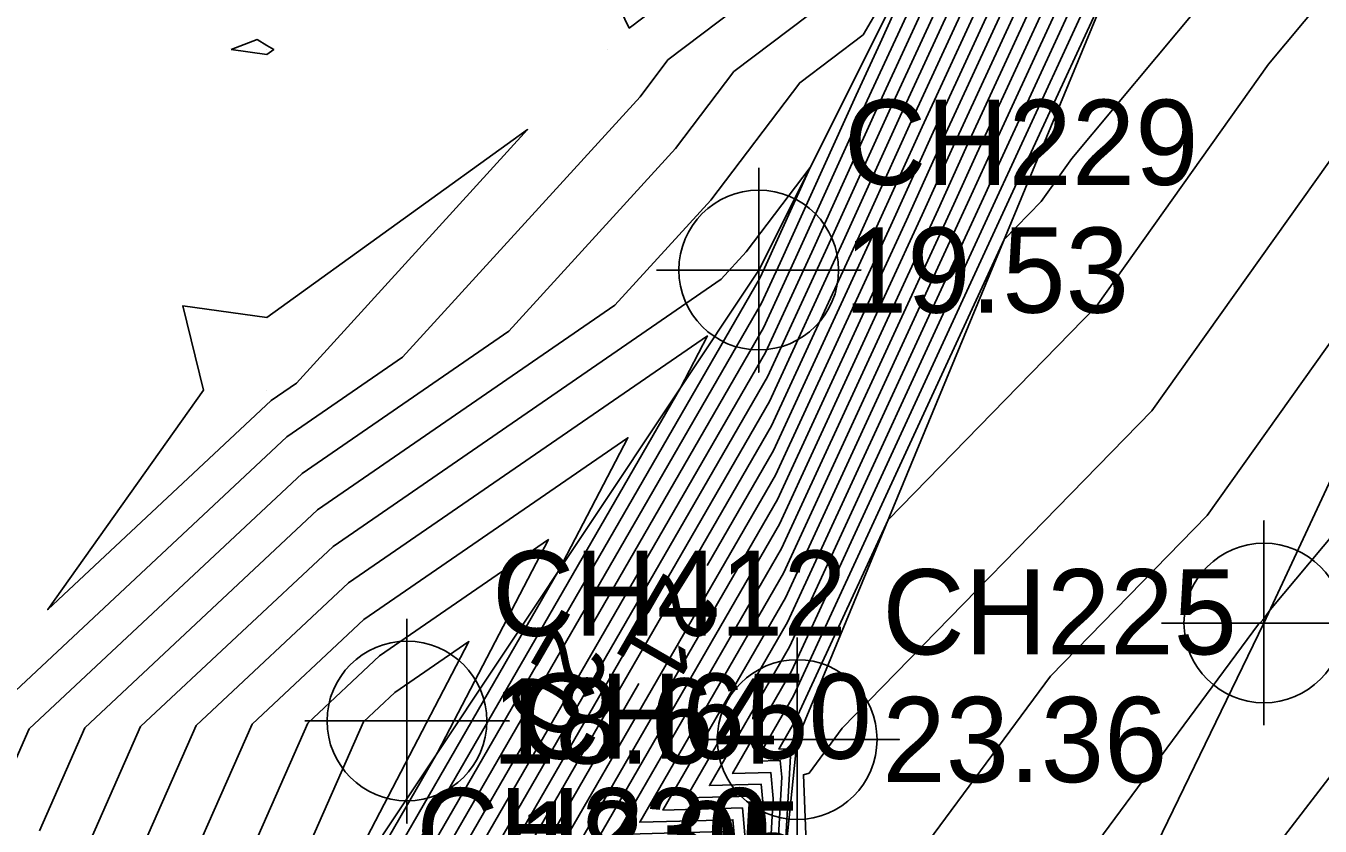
# Model space of a CAD drawing. Extents: x 2531902 to 2533249, y 715219 to 716099.
# Drawn here: x 2532842.92 to 2532880.91, y 715667.21 to 715690.69 of the extents above; entities that cross this region are included whole.
import ezdxf

# ---------------------------------------------------------------- set-up
doc = ezdxf.new("R2010")
doc.units = 0
for name, color, linetype in [('DTM Contours Major', 7, 'Continuous'), ('DTM Contours Major Text', 7, 'Continuous'), ('DTM Contours Minor', 7, 'Continuous'), ('Exist DTM Breakline', 7, 'Continuous'), ('Exist DTM Breakline Cogo Elevation', 7, 'Continuous'), ('Exist DTM Breakline Cogo Number', 7, 'Continuous'), ('Exist DTM Breakline Cogo Point CELL', 7, 'Continuous'), ('Exist DTM QL2 LIDAR Elevation Point', 7, 'Continuous'), ('Exist DTM Regular Point CELL', 7, 'Continuous'), ('Exist DTM Regular Point Cogo Elevation', 7, 'Continuous'), ('Exist DTM Regular Point Cogo Number', 7, 'Continuous'), ('Exist Roads Soil', 7, 'Continuous'), ('Exist Roads Soil Cogo Point CELL', 7, 'Continuous')]:
    doc.layers.add(name, color=color, linetype=linetype)

msp = doc.modelspace()

# ---------------------------------------------------------------- linework, layer by layer
at = {"layer": 'DTM Contours Major'}
for points in [[(2532893.313, 715749.337), (2532899.157, 715757.294), (2532891.649, 715737.361), (2532888.467, 715730.76), (2532884.29, 715720.393), (2532881.681, 715715), (2532875.656, 715701.654), (2532869.225, 715687.729), (2532867.839, 715684.677), (2532864.865, 715678.232), (2532862.915, 715674.854)], [(2532880.417, 715707.702), (2532870.834, 715686.951), (2532870.156, 715685.459), (2532865.159, 715674.632), (2532860.94, 715667.321), (2532863.673, 715667.393), (2532863.838, 715665.539), (2532863.575, 715660.867), (2532863.5, 715660.175), (2532863.284, 715660.391), (2532863.242, 715660.351), (2532863.077, 715658.749), (2532865.019, 715656.53), (2532866.863, 715655.862), (2532867.314, 715655.698), (2532867.762, 715655.577), (2532869.107, 715654.928), (2532869.992, 715654.403), (2532870.491, 715654.162), (2532874.102, 715652.417), (2532878.683, 715650.288), (2532879.268, 715650.005), (2532882.822, 715648.289)], [(2532833.041, 715658.953), (2532836.467, 715658.82), (2532841.725, 715659.565), (2532841.817, 715660.266), (2532842.154, 715668.099), (2532843.02, 715670.063), (2532851.032, 715677.56), (2532857.094, 715681.734), (2532861.988, 715687.097), (2532863.701, 715689.359), (2532868.079, 715692.676), (2532874.442, 715703.544), (2532869.274, 715692.097), (2532867.616, 715688.507), (2532865.522, 715683.895), (2532864.57, 715681.832), (2532859.473, 715672.999)], [(2532882.32, 715697.223), (2532873.621, 715686.805), (2532872.723, 715685.542), (2532871.636, 715684.428), (2532865.454, 715671.033), (2532864.344, 715669.11), (2532865.063, 715669.129), (2532865.106, 715668.642), (2532864.691, 715661.251)], [(2532787.963, 715647.113), (2532788.11, 715647.155), (2532790.468, 715647.623), (2532805.524, 715651.812), (2532807.289, 715651.681), (2532812.395, 715655.613), (2532820.905, 715653.907), (2532825.351, 715654.892), (2532826.014, 715655.145), (2532830.295, 715655.728), (2532841.623, 715657.272), (2532847.51, 715658.105), (2532847.908, 715661.158), (2532847.985, 715662.951), (2532851.196, 715670.232), (2532853.299, 715672.201), (2532858.259, 715675.616), (2532855.007, 715669.369), (2532850.728, 715661.954), (2532851.349, 715661.97)], [(2532886.148, 715672.294), (2532885.122, 715673.441), (2532882.141, 715669.883), (2532871.882, 715656.546), (2532870.966, 715655.228), (2532874.68, 715653.03)], [(2532860.916, 715671.39), (2532857.536, 715665.532), (2532862.284, 715665.656), (2532862.57, 715662.436), (2532862.526, 715661.663), (2532862.514, 715661.549), (2532862.467, 715661.596), (2532862.044, 715661.075), (2532862.24, 715660.903), (2532862.104, 715659.587), (2532865.09, 715656.174), (2532866.383, 715655.706), (2532867.084, 715655.452), (2532867.782, 715655.264), (2532868.726, 715654.808), (2532870.098, 715653.994), (2532870.449, 715653.824), (2532872.982, 715652.6), (2532880.052, 715649.314), (2532880.463, 715649.116), (2532882.956, 715647.912)], [(2532857.474, 715669.534), (2532854.132, 715663.743), (2532860.894, 715663.92), (2532861.07, 715661.935), (2532860.771, 715661.566), (2532861.209, 715661.181), (2532861.131, 715660.425), (2532865.16, 715655.819), (2532865.903, 715655.55), (2532866.855, 715655.206), (2532867.802, 715654.95), (2532868.344, 715654.688), (2532870.205, 715653.584), (2532870.406, 715653.487), (2532871.862, 715652.783), (2532881.422, 715648.34)]]:
    msp.add_lwpolyline(points, dxfattribs=at)
at = {"layer": 'DTM Contours Minor'}
for points in [[(2532883.314, 715713.121), (2532871.155, 715686.796), (2532870.619, 715685.615), (2532865.218, 715673.912), (2532861.621, 715667.679), (2532863.951, 715667.74), (2532864.092, 715666.16), (2532863.785, 715660.708), (2532863.697, 715659.9), (2532863.505, 715660.093), (2532863.419, 715660.011), (2532863.272, 715658.582), (2532865.005, 715656.601), (2532866.959, 715655.893), (2532867.36, 715655.748), (2532867.759, 715655.64), (2532869.184, 715654.952), (2532869.97, 715654.485), (2532870.5, 715654.229), (2532874.326, 715652.38), (2532878.409, 715650.483), (2532879.029, 715650.183), (2532882.795, 715648.364)], [(2532880.761, 715709.299), (2532870.512, 715687.107), (2532869.693, 715685.302), (2532865.1, 715675.352), (2532860.259, 715666.963), (2532863.395, 715667.045), (2532863.584, 715664.919), (2532863.365, 715661.027), (2532863.303, 715660.45), (2532863.066, 715660.687), (2532863.062, 715660.682), (2532863.064, 715660.68), (2532862.883, 715658.917), (2532865.033, 715656.459), (2532866.767, 715655.83), (2532867.268, 715655.649), (2532867.766, 715655.515), (2532869.031, 715654.904), (2532870.013, 715654.321), (2532870.483, 715654.094), (2532873.878, 715652.454), (2532878.957, 715650.093), (2532879.507, 715649.827), (2532882.849, 715648.213)], [(2532881.859, 715709.12), (2532871.477, 715686.64), (2532871.083, 715685.772), (2532865.277, 715673.192), (2532862.302, 715668.037), (2532864.229, 715668.087), (2532864.345, 715666.78), (2532863.995, 715660.549), (2532863.894, 715659.626), (2532863.726, 715659.795), (2532863.596, 715659.672), (2532863.467, 715658.414), (2532864.991, 715656.672), (2532867.055, 715655.924), (2532867.406, 715655.797), (2532867.755, 715655.703), (2532869.26, 715654.976), (2532869.949, 715654.567), (2532870.508, 715654.297), (2532874.55, 715652.344), (2532878.135, 715650.678), (2532878.79, 715650.361), (2532882.768, 715648.44)], [(2532879.485, 715707.387), (2532870.19, 715687.263), (2532869.229, 715685.146), (2532865.041, 715676.072), (2532859.579, 715666.606), (2532863.117, 715666.698), (2532863.331, 715664.298), (2532863.156, 715661.186), (2532863.105, 715660.725), (2532862.917, 715660.914), (2532862.808, 715660.78), (2532862.858, 715660.736), (2532862.688, 715659.085), (2532865.047, 715656.388), (2532866.671, 715655.799), (2532867.222, 715655.6), (2532867.77, 715655.452), (2532868.955, 715654.88), (2532870.034, 715654.239), (2532870.474, 715654.027), (2532873.654, 715652.49), (2532879.231, 715649.898), (2532879.746, 715649.649), (2532882.875, 715648.138)], [(2532878.208, 715705.476), (2532869.868, 715687.418), (2532868.766, 715684.99), (2532864.982, 715676.792), (2532858.898, 715666.248), (2532862.839, 715666.351), (2532863.077, 715663.677), (2532862.946, 715661.345), (2532862.908, 715660.999), (2532862.767, 715661.141), (2532862.553, 715660.878), (2532862.652, 715660.791), (2532862.494, 715659.252), (2532865.061, 715656.317), (2532866.575, 715655.768), (2532867.176, 715655.551), (2532867.774, 715655.389), (2532868.878, 715654.856), (2532870.056, 715654.157), (2532870.466, 715653.959), (2532873.43, 715652.527), (2532879.505, 715649.704), (2532879.985, 715649.471), (2532882.902, 715648.063)], [(2532876.932, 715703.565), (2532869.547, 715687.574), (2532868.303, 715684.833), (2532864.923, 715677.512), (2532858.217, 715665.89), (2532862.562, 715666.004), (2532862.823, 715663.057), (2532862.736, 715661.504), (2532862.711, 715661.274), (2532862.617, 715661.368), (2532862.299, 715660.976), (2532862.446, 715660.847), (2532862.299, 715659.42), (2532865.076, 715656.245), (2532866.479, 715655.737), (2532867.13, 715655.501), (2532867.778, 715655.326), (2532868.802, 715654.832), (2532870.077, 715654.075), (2532870.457, 715653.892), (2532873.206, 715652.564), (2532879.779, 715649.509), (2532880.224, 715649.294), (2532882.929, 715647.987)], [(2532878.451, 715700.889), (2532871.799, 715686.484), (2532871.546, 715685.928), (2532865.336, 715672.472), (2532862.983, 715668.395), (2532864.507, 715668.435), (2532864.599, 715667.401), (2532864.205, 715660.39), (2532864.092, 715659.351), (2532863.947, 715659.496), (2532863.773, 715659.332), (2532863.661, 715658.247), (2532864.977, 715656.743), (2532867.151, 715655.955), (2532867.452, 715655.846), (2532867.751, 715655.765), (2532869.336, 715655), (2532869.928, 715654.649), (2532870.517, 715654.364), (2532874.774, 715652.307), (2532877.861, 715650.873), (2532878.551, 715650.539), (2532882.741, 715648.515)], [(2532874.379, 715699.742), (2532868.903, 715687.885), (2532867.376, 715684.52), (2532864.806, 715678.952), (2532856.855, 715665.174), (2532862.006, 715665.309), (2532862.315, 715661.821), (2532861.789, 715661.173), (2532862.034, 715660.958), (2532861.91, 715659.755), (2532865.104, 715656.103), (2532866.287, 715655.675), (2532867.038, 715655.403), (2532867.786, 715655.201), (2532868.649, 715654.784), (2532870.12, 715653.912), (2532870.44, 715653.757), (2532872.758, 715652.637), (2532880.326, 715649.119), (2532880.702, 715648.938), (2532882.983, 715647.836)], [(2532887.67, 715699.481), (2532879.396, 715689.571), (2532874.346, 715682.468), (2532868.229, 715676.197), (2532865.512, 715670.313), (2532865.025, 715669.468), (2532865.341, 715669.476), (2532865.36, 715669.262), (2532865.177, 715666.015)], [(2532873.103, 715697.831), (2532868.581, 715688.041), (2532866.912, 715684.364), (2532864.747, 715679.672), (2532856.175, 715664.816), (2532861.728, 715664.962), (2532862.004, 715661.85), (2532861.535, 715661.271), (2532861.827, 715661.014), (2532861.715, 715659.922), (2532865.118, 715656.032), (2532866.191, 715655.644), (2532866.992, 715655.353), (2532867.79, 715655.138), (2532868.573, 715654.76), (2532870.141, 715653.83), (2532870.432, 715653.689), (2532872.534, 715652.674), (2532880.6, 715648.924), (2532880.941, 715648.76)], [(2532860, 715691.942), (2532860.63, 715690.63), (2532869.256, 715697.164)], [(2532871.827, 715695.92), (2532868.26, 715688.196), (2532866.449, 715684.208), (2532864.688, 715680.392), (2532855.494, 715664.459), (2532861.45, 715664.615), (2532861.693, 715661.878), (2532861.28, 715661.37), (2532861.621, 715661.07), (2532861.521, 715660.09), (2532865.132, 715655.961), (2532866.095, 715655.613), (2532866.947, 715655.304), (2532867.794, 715655.075), (2532868.496, 715654.736), (2532870.162, 715653.748), (2532870.423, 715653.622), (2532872.31, 715652.71), (2532880.874, 715648.73), (2532881.18, 715648.582)], [(2532841.385, 715670.029), (2532850.579, 715678.632), (2532853.978, 715680.972), (2532860.95, 715688.613), (2532861.768, 715689.694), (2532868.668, 715694.92)], [(2532843.32, 715667.069), (2532844.655, 715670.097), (2532851.486, 715676.488), (2532860.21, 715682.495), (2532863.025, 715685.58), (2532865.633, 715689.024), (2532867.491, 715690.431), (2532870.19, 715695.042), (2532867.998, 715690.186), (2532867.294, 715688.663), (2532865.059, 715683.739), (2532864.511, 715682.552), (2532853.451, 715663.385)], [(2532870.55, 715694.009), (2532867.938, 715688.352), (2532865.986, 715684.051), (2532864.629, 715681.112), (2532854.813, 715664.101), (2532861.172, 715664.267), (2532861.381, 715661.907), (2532861.025, 715661.468), (2532861.415, 715661.125), (2532861.326, 715660.258), (2532865.146, 715655.89), (2532865.999, 715655.581), (2532866.901, 715655.255), (2532867.798, 715655.013), (2532868.42, 715654.712), (2532870.184, 715653.666), (2532870.415, 715653.554), (2532872.086, 715652.747), (2532881.148, 715648.535)], [(2532875.044, 715692.658), (2532872.121, 715686.329), (2532872.01, 715686.084), (2532865.395, 715671.752), (2532863.664, 715668.752), (2532864.785, 715668.782), (2532864.853, 715668.021), (2532864.415, 715660.231), (2532864.289, 715659.076), (2532864.167, 715659.198), (2532863.95, 715658.992), (2532863.856, 715658.079), (2532864.963, 715656.814), (2532867.247, 715655.986), (2532867.497, 715655.896), (2532867.747, 715655.828), (2532869.413, 715655.024), (2532869.906, 715654.731), (2532870.525, 715654.432), (2532874.998, 715652.27), (2532877.587, 715651.067), (2532878.312, 715650.717), (2532882.714, 715648.591)], [(2532885.17, 715692.337), (2532875.969, 715679.394), (2532866.881, 715670.079), (2532865.908, 715668.764), (2532865.744, 715668.717), (2532866.143, 715658.451), (2532865.804, 715657.885), (2532864.948, 715658.865), (2532864.881, 715658.252), (2532864.83, 715658.303), (2532864.48, 715657.973), (2532864.44, 715657.576), (2532864.92, 715657.027), (2532867.535, 715656.08), (2532867.635, 715656.043), (2532867.735, 715656.016)], [(2532848.945, 715690), (2532849.709, 715690.291), (2532850, 715690.122), (2532850.2, 715690), (2532850, 715689.856), (2532848.945, 715690)], [(2532886.706, 715689.14), (2532877.592, 715676.32), (2532872.992, 715671.605), (2532867.523, 715664.214), (2532866.601, 715663.952), (2532866.843, 715657.71), (2532866.493, 715657.125), (2532866.576, 715656.958), (2532866.088, 715657.149), (2532865.95, 715657.353), (2532865.114, 715658.31), (2532865.078, 715657.977), (2532865.05, 715658.005), (2532864.657, 715657.633), (2532864.634, 715657.409), (2532864.906, 715657.098), (2532867.631, 715656.111), (2532867.681, 715656.093), (2532867.731, 715656.079)], [(2532850.125, 715679.703), (2532850.862, 715680.211), (2532857.649, 715687.649), (2532850, 715682.136), (2532847.526, 715682.474), (2532848.133, 715680), (2532843.565, 715673.565), (2532850.125, 715679.703)], [(2532844.486, 715666.04), (2532846.29, 715670.131), (2532851.939, 715675.416), (2532863.327, 715683.257), (2532864.063, 715684.064), (2532865.939, 715686.541), (2532864.596, 715683.582), (2532864.452, 715683.271), (2532852.771, 715663.027)], [(2532886.819, 715682.372), (2532879.437, 715673.559), (2532879.214, 715673.246), (2532879.102, 715673.131), (2532869.138, 715659.665), (2532867.457, 715659.187), (2532867.543, 715656.97), (2532867.419, 715656.762), (2532867.727, 715656.142), (2532867.72, 715656.145), (2532865.633, 715656.976), (2532865.686, 715657.197), (2532865.411, 715657.606), (2532865.281, 715657.754), (2532865.275, 715657.703), (2532865.271, 715657.707), (2532864.834, 715657.293), (2532864.829, 715657.241), (2532864.892, 715657.169), (2532867.727, 715656.142), (2532867.727, 715656.142), (2532867.727, 715656.142)], [(2532829.359, 715656.447), (2532845.196, 715658.689), (2532845.471, 715660.801), (2532845.653, 715665.01), (2532847.925, 715670.165), (2532852.393, 715674.344), (2532862.925, 715681.596), (2532862.132, 715680.072), (2532852.09, 715662.669), (2532860.06, 715662.878), (2532860.136, 715662.02), (2532860.007, 715661.861), (2532860.591, 715661.348), (2532860.547, 715660.928), (2532865.203, 715655.606), (2532865.615, 715655.457), (2532866.717, 715655.058), (2532867.813, 715654.762), (2532868.115, 715654.616), (2532870.269, 715653.338), (2532870.381, 715653.284), (2532871.189, 715652.893), (2532882.244, 715647.755)], [(2532826.99, 715655.656), (2532846.353, 715658.397), (2532846.69, 715660.979), (2532846.819, 715663.981), (2532849.561, 715670.199), (2532852.846, 715673.273), (2532860.592, 715678.606), (2532858.569, 715674.721), (2532851.409, 715662.312), (2532859.782, 715662.531), (2532859.825, 715662.049), (2532859.752, 715661.959), (2532860.385, 715661.404), (2532860.353, 715661.096), (2532865.217, 715655.535), (2532865.519, 715655.426), (2532866.671, 715655.009), (2532867.817, 715654.699), (2532868.038, 715654.592), (2532870.291, 715653.256), (2532870.373, 715653.217), (2532870.965, 715652.93), (2532882.518, 715647.561)], [(2532849.151, 715661.922), (2532852.831, 715670.266), (2532853.753, 715671.129), (2532855.926, 715672.625), (2532851.445, 715664.018)]]:
    msp.add_lwpolyline(points, dxfattribs=at)
at = {"layer": 'Exist DTM Breakline'}
for points in [[(2533029.092, 715973.615), (2533002.141, 715931.719), (2532981.109, 715895.925), (2532963.783, 715865.168), (2532944.31, 715831.075), (2532924.281, 715797.496), (2532904.489, 715756.171), (2532883.846, 715713.918), (2532865.559, 715669.748), (2532864.574, 715660.11), (2532866.15, 715657.26), (2532867.929, 715656.562)], [(2533023.854, 715972.817), (2532999.029, 715934.39), (2532976.745, 715897.826), (2532959.919, 715867.589), (2532939.765, 715833.591), (2532921.006, 715799.338), (2532899.767, 715758.656), (2532880.473, 715715.603), (2532864.431, 715683.527), (2532849.717, 715661.422)]]:
    msp.add_lwpolyline(points, dxfattribs=at)
at = {"layer": 'Exist DTM Breakline Cogo Point CELL'}
for points in [[(2532864.431, 715686.527), (2532864.431, 715680.527), (2532864.431, 715683.527), (2532867.431, 715683.527), (2532861.431, 715683.527)], [(2532865.559, 715672.748), (2532865.559, 715666.748), (2532865.559, 715669.748), (2532868.559, 715669.748), (2532862.559, 715669.748)]]:
    msp.add_lwpolyline(points, dxfattribs=at)
for centre in [(2532864.431, 715683.527), (2532865.559, 715669.748)]:
    msp.add_circle(centre, 2.344, dxfattribs=at)
at = {"layer": 'Exist DTM QL2 LIDAR Elevation Point'}
for p, q in [((2532850, 715690), (2532850, 715690)), ((2532860, 715690), (2532860, 715690)), ((2532850, 715680), (2532850, 715680))]:
    msp.add_line(p, q, dxfattribs=at)
at = {"layer": 'Exist DTM Regular Point CELL'}
msp.add_lwpolyline([(2532854.107, 715673.293), (2532854.107, 715667.293), (2532854.107, 715670.293), (2532857.107, 715670.293), (2532851.107, 715670.293)], dxfattribs=at)
msp.add_circle((2532854.107, 715670.293), 2.344, dxfattribs=at)
at = {"layer": 'Exist Roads Soil'}
msp.add_lwpolyline([(2533033.002, 715963.552), (2533014.441, 715935.484), (2532992.666, 715901.095), (2532976.471, 715871.314), (2532962.05, 715845.129), (2532943.271, 715807.995), (2532921.982, 715764.363), (2532902.685, 715724.284), (2532889.068, 715694.204), (2532879.255, 715673.169), (2532870.648, 715655.411), (2532876.571, 715652.013), (2532882.435, 715649.375)], dxfattribs=at)
at = {"layer": 'Exist Roads Soil Cogo Point CELL'}
msp.add_lwpolyline([(2532879.255, 715670.169), (2532879.255, 715676.169), (2532879.255, 715673.169), (2532882.255, 715673.169), (2532876.255, 715673.169)], dxfattribs=at)
msp.add_circle((2532879.255, 715673.169), 2.344, dxfattribs=at)

# ---------------------------------------------------------------- texts
at = {"layer": 'DTM Contours Major Text'}
for s, p in [('21', (2532861.695, 715674.74)), ('20', (2532858.422, 715673.178))]:
    msp.add_text(s, height=2, rotation=240.0135, dxfattribs=at).set_placement(p)
at = {"layer": 'Exist DTM Breakline Cogo Elevation'}
for s, p in [('19.53', (2532866.931, 715682.277)), ('23.36', (2532868.059, 715668.498))]:
    msp.add_text(s, height=2.5, dxfattribs=at).set_placement(p)
at = {"layer": 'Exist DTM Breakline Cogo Number'}
for s, p in [('CH229', (2532866.931, 715686.027)), ('CH225', (2532868.059, 715672.248)), ('CH230', (2532854.383, 715665.824))]:
    msp.add_text(s, height=2.5, dxfattribs=at).set_placement(p)
at = {"layer": 'Exist DTM Regular Point Cogo Elevation'}
for s, p in [('18.64', (2532856.607, 715669.043)), ('18.95', (2532857.346, 715665.435))]:
    msp.add_text(s, height=2.5, dxfattribs=at).set_placement(p)
at = {"layer": 'Exist DTM Regular Point Cogo Number'}
for s, p in [('CH412', (2532856.607, 715672.793)), ('CH650', (2532857.346, 715669.185))]:
    msp.add_text(s, height=2.5, dxfattribs=at).set_placement(p)

doc.saveas('drawing.dxf')
